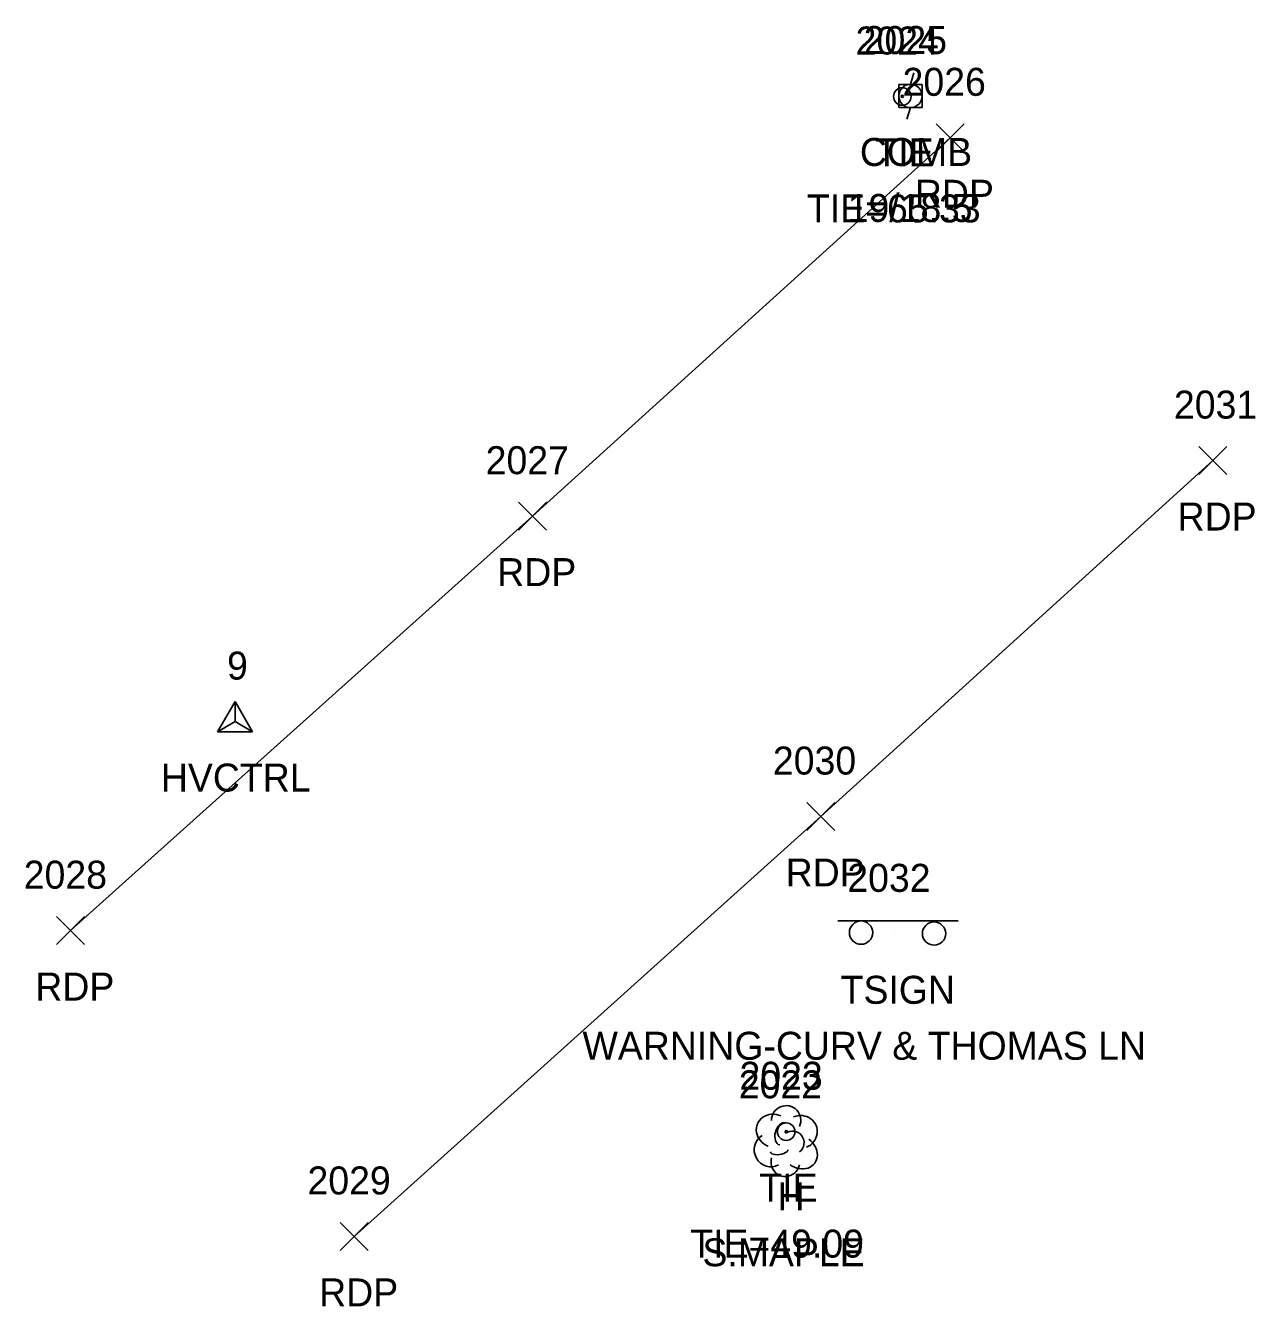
# Model space of a CAD drawing. Extents: x 1497084 to 1499861, y 734741 to 735567.
# Drawn here: x 1497084.2 to 1497172, y 734741.4 to 734832.9 of the extents above; entities that cross this region are included whole.
import ezdxf

# ---------------------------------------------------------------- set-up
doc = ezdxf.new("R2010")
doc.units = 0
for name, color, linetype in [('C_A', 7, 'Continuous'), ('C_C', 7, 'Continuous'), ('C_I', 7, 'Continuous'), ('CBP', 7, 'Continuous'), ('CPSM', 7, 'Continuous'), ('L_A', 7, 'Continuous'), ('L_C', 7, 'Continuous'), ('L_I', 7, 'Continuous'), ('LTD', 7, 'Continuous'), ('P_A', 7, 'Continuous'), ('P_I', 7, 'Continuous'), ('P_TIC', 7, 'Continuous'), ('PET', 7, 'Continuous'), ('S_A', 7, 'Continuous'), ('S_C', 7, 'Continuous'), ('S_I', 7, 'Continuous'), ('SSGN', 7, 'Continuous'), ('U_A', 7, 'Continuous'), ('U_C', 7, 'Continuous'), ('U_I', 7, 'Continuous'), ('UP', 7, 'Continuous')]:
    doc.layers.add(name, color=color, linetype=linetype)

msp = doc.modelspace()

# ---------------------------------------------------------------- linework, layer by layer
at = {"layer": 'CBP'}
for centre, radius in [((1497146.811, 734827.849), 0.625), ((1497146.811, 734827.849), 0.0833), ((1497138.514, 734753.868), 0.625), ((1497138.514, 734753.868), 0.0833)]:
    msp.add_circle(centre, radius, dxfattribs=at)
at = {"layer": 'CPSM'}
for p, q in [((1497097.885, 734782.455), (1497099.135, 734784.62)), ((1497100.385, 734782.455), (1497099.135, 734784.62)), ((1497099.135, 734783.176), (1497099.135, 734784.62)), ((1497097.885, 734782.455), (1497099.135, 734783.176)), ((1497097.885, 734782.455), (1497100.385, 734782.455)), ((1497099.135, 734783.176), (1497099.135, 734783.176)), ((1497099.135, 734783.176), (1497100.385, 734782.455))]:
    msp.add_line(p, q, dxfattribs=at)
at = {"layer": 'LTD'}
msp.add_line((1497138.464, 734753.251), (1497138.464, 734753.251), dxfattribs=at)
msp.add_line((1497138.464, 734753.251), (1497138.464, 734753.251), dxfattribs=at)
msp.add_arc((1497138.511, 734754.684), 1.047, 335.52715, 180.95627, dxfattribs=at)
for centre, major_axis, ratio, start_param, end_param in [((1497137.672, 734753.917), (1.21, -0.512), 0.895232, 1.570796, 4.712389), ((1497139.505, 734753.834), (-1.141, -0.483), 0.949671, 1.570796, 4.712389), ((1497138.255, 734753.709), (-0.208, -0.792), 0.645439, 3.141593, 6.283185), ((1497138.964, 734753.084), (-0.5, 0.667), 0.989748, 3.141593, 6.283185), ((1497137.381, 734752.542), (0.584, -1.042), 0.959034, 3.141593, 6.283185), ((1497139.464, 734752.417), (-1.09, 0.792), 0.841452, 1.570796, 4.712389), ((1497138.006, 734752.5), (-0.625, -0.083), 0.423636, 0, 3.141593), ((1497138.464, 734751.751), (0.265, 1.061), 0.942809, 1.570796, 4.712389)]:
    msp.add_ellipse(centre, major_axis=major_axis, ratio=ratio, start_param=start_param, end_param=end_param, dxfattribs=at)
at = {"layer": 'P_TIC'}
for points in [[(1497149.223, 734823.897), (1497151.223, 734825.897)], [(1497151.223, 734823.897), (1497149.223, 734825.897)], [(1497167.993, 734800.83), (1497169.993, 734802.83)], [(1497169.993, 734800.83), (1497167.993, 734802.83)], [(1497119.376, 734796.855), (1497121.376, 734798.855)], [(1497121.376, 734796.855), (1497119.376, 734798.855)], [(1497139.988, 734775.391), (1497141.988, 734777.391)], [(1497141.988, 734775.391), (1497139.988, 734777.391)], [(1497086.368, 734767.236), (1497088.368, 734769.236)], [(1497088.368, 734767.236), (1497086.368, 734769.236)], [(1497106.651, 734745.383), (1497108.651, 734747.383)], [(1497108.651, 734745.383), (1497106.651, 734747.383)]]:
    msp.add_lwpolyline(points, dxfattribs=at)
at = {"layer": 'PET'}
for points in [[(1497150.223, 734824.897), (1497120.376, 734797.855), (1497087.368, 734768.236)], [(1497107.651, 734746.383), (1497140.988, 734776.391), (1497168.993, 734801.83)]]:
    msp.add_lwpolyline(points, dxfattribs=at)
at = {"layer": 'SSGN'}
for p, q in [((1497142.202, 734768.929), (1497150.799, 734768.929)), ((1497146.224, 734768.026), (1497146.224, 734768.026))]:
    msp.add_line(p, q, dxfattribs=at)
for centre in [(1497143.863, 734768.096), (1497149.078, 734768.026)]:
    msp.add_circle(centre, 0.833, dxfattribs=at)
at = {"layer": 'UP'}
for p, q in [((1497147.642, 734829.551), (1497147.392, 734828.717)), ((1497146.558, 734827.051), (1497146.558, 734828.717)), ((1497146.558, 734828.717), (1497148.225, 734828.717)), ((1497148.225, 734828.717), (1497148.225, 734827.051)), ((1497147.392, 734827.884), (1497147.392, 734827.884)), ((1497148.225, 734827.051), (1497146.558, 734827.051)), ((1497147.142, 734826.217), (1497147.392, 734827.051))]:
    msp.add_line(p, q, dxfattribs=at)
msp.add_circle((1497147.392, 734827.884), 0.833, dxfattribs=at)

# ---------------------------------------------------------------- texts
at = {"layer": 'C_A'}
for s, p in [('TIE', (1497144.89, 734822.849)), ('HVCTRL', (1497093.828, 734778.176)), ('TIE', (1497136.593, 734748.868))]:
    msp.add_text(s, height=2, dxfattribs=at).set_placement(p)
at = {"layer": 'C_C'}
for s, p in [('TIE=65.33', (1497139.992, 734818.849)), ('TIE=49.09', (1497131.656, 734744.868))]:
    msp.add_text(s, height=2, dxfattribs=at).set_placement(p)
at = {"layer": 'C_I'}
for s, p in [('2024', (1497143.473, 734830.849)), ('9', (1497098.56, 734786.176)), ('2023', (1497135.175, 734756.868))]:
    msp.add_text(s, height=2, dxfattribs=at).set_placement(p)
at = {"layer": 'L_A'}
msp.add_text('H', height=2, dxfattribs=at).set_placement((1497137.897, 734748.251))
at = {"layer": 'L_C'}
msp.add_text('S.MAPLE', height=2, dxfattribs=at).set_placement((1497132.527, 734744.251))
at = {"layer": 'L_I'}
msp.add_text('2022', height=2, dxfattribs=at).set_placement((1497135.125, 734756.251))
at = {"layer": 'P_A'}
for p in [(1497147.711, 734819.897), (1497166.481, 734796.83), (1497117.864, 734792.855), (1497138.476, 734771.391), (1497084.856, 734763.236), (1497105.14, 734741.383)]:
    msp.add_text('RDP', height=2, dxfattribs=at).set_placement(p)
at = {"layer": 'P_I'}
for s, p in [('2026', (1497146.83, 734827.897)), ('2031', (1497166.221, 734804.83)), ('2027', (1497117.038, 734800.855)), ('2030', (1497137.563, 734779.391)), ('2028', (1497084.029, 734771.236)), ('2029', (1497104.305, 734749.383))]:
    msp.add_text(s, height=2, dxfattribs=at).set_placement(p)
at = {"layer": 'S_A'}
msp.add_text('TSIGN', height=2, dxfattribs=at).set_placement((1497142.4, 734763.008))
at = {"layer": 'S_C'}
msp.add_text('WARNING-CURV & THOMAS LN', height=2, dxfattribs=at).set_placement((1497123.959, 734759.008))
at = {"layer": 'S_I'}
msp.add_text('2032', height=2, dxfattribs=at).set_placement((1497142.88, 734771.008))
at = {"layer": 'U_A'}
msp.add_text('COMB', height=2, dxfattribs=at).set_placement((1497143.778, 734822.884))
at = {"layer": 'U_C'}
msp.add_text('19/18.5', height=2, dxfattribs=at).set_placement((1497142.904, 734818.884))
at = {"layer": 'U_I'}
msp.add_text('2025', height=2, dxfattribs=at).set_placement((1497144.053, 734830.884))

doc.saveas('drawing.dxf')
